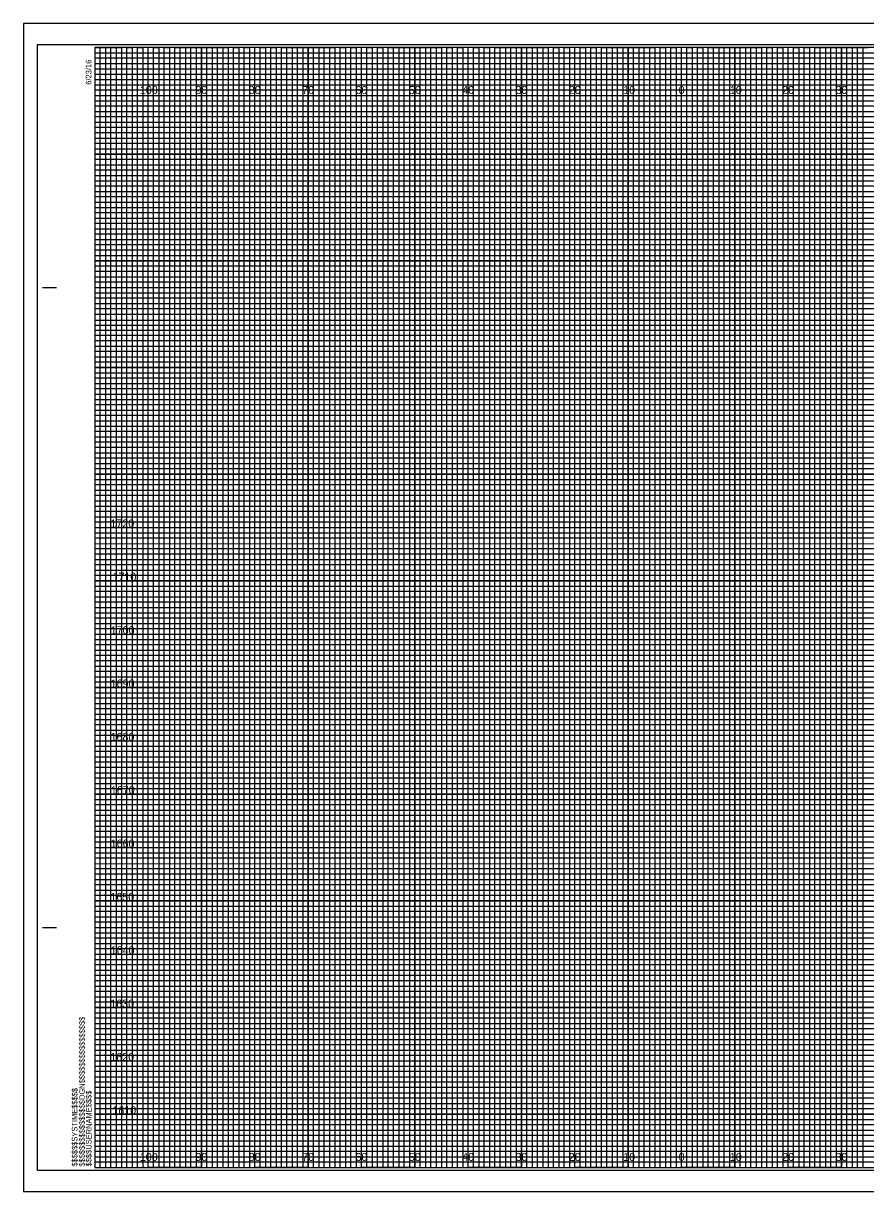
# Model space of a CAD drawing. Extents: x -13 to 323, y -5 to 6154.
# Drawn here: x -13.4 to 144.5, y 3515.5 to 3734.5 of the extents above; entities that cross this region are included whole.
import ezdxf

# ---------------------------------------------------------------- set-up
doc = ezdxf.new("R2010")
doc.units = 0
for name, color, linetype in [('Prop Retaining Wall', 7, 'Continuous'), ('Prop XS Alignment Label', 7, 'Continuous'), ('Prop XS DDE', 7, 'Continuous'), ('Prop XS DDE Elevations', 7, 'Continuous'), ('Prop XS DDE Slope Text', 7, 'Continuous'), ('Prop XS Earthwork Shape', 7, 'Continuous'), ('Prop XS Elevation Labels', 7, 'Continuous'), ('Prop XS Station Labels', 7, 'Continuous'), ('Raster_Level_0', 7, 'Continuous'), ('Scratch_Level_3', 7, 'Continuous'), ('Sheet Cutting Line CELL', 7, 'Continuous')]:
    doc.layers.add(name, color=color, linetype=linetype)

msp = doc.modelspace()

# ---------------------------------------------------------------- linework, layer by layer
at = {"layer": 'Prop Retaining Wall'}
for p, q in [((0, 3729), (260, 3729)), ((260, 3727.98), (0, 3727.98)), ((0, 3727.98), (0, 3727)), ((0, 3727), (260, 3727)), ((260, 3725.89), (0, 3725.89)), ((0, 3725.89), (0, 3724)), ((0, 3724), (320, 3724))]:
    msp.add_line(p, q, dxfattribs=at)
for points in [[(0, 3723), (270, 3723), (320, 3723), (320, 3722), (0, 3722)], [(0, 3721), (320, 3721), (320, 3719), (0, 3719)], [(0, 3718), (320, 3718), (320, 3717), (0, 3716.98)], [(0, 3716), (320, 3716), (320, 3714), (0, 3714)], [(0, 3713), (320, 3713), (320, 3712), (0, 3712)], [(0, 3711), (320, 3711), (320, 3709), (0, 3709)], [(0, 3708), (320, 3708), (320, 3707), (0, 3707)], [(0, 3706), (320, 3706), (320, 3704), (0, 3704)], [(0, 3703), (320, 3703), (320, 3702), (0, 3702)], [(0, 3701), (320, 3701), (320, 3699), (0, 3699)], [(0, 3698), (320, 3698), (320, 3697), (0, 3697)], [(0, 3696), (320, 3696), (320, 3693.95), (320, 3693), (320, 3692), (0, 3692)], [(0, 3694), (320, 3694), (320, 3693), (0, 3693)], [(0, 3691), (320, 3691), (320, 3689), (0, 3689.03)], [(0, 3689.03), (320, 3689), (320, 3688), (0, 3688)], [(0, 3687), (320, 3687), (320, 3686), (0, 3686)], [(0, 3684), (320, 3684), (320, 3683), (0, 3683)], [(0, 3682), (320, 3682), (320, 3681), (0, 3681)], [(-0.07, 3678.89), (320, 3678.89), (320, 3677.88), (-0.07, 3677.88)], [(0, 3677), (320, 3677), (320, 3676), (0, 3676)], [(0, 3674), (320, 3674), (320, 3673), (0, 3673)], [(0, 3672), (320, 3672), (320, 3671), (0, 3671)], [(0, 3669), (320, 3669), (320, 3668), (0, 3668)], [(0, 3667), (320, 3667), (320, 3666), (0, 3666)], [(0, 3664), (320, 3664), (320, 3663), (0, 3663)], [(0, 3662), (320, 3662), (320, 3661), (0, 3661)], [(0, 3659), (320, 3659), (319.99, 3657.98), (0, 3658)], [(0, 3657), (320, 3657), (320, 3656), (0, 3656)], [(0, 3654), (320, 3654), (320, 3653), (0, 3653)], [(0, 3652), (320, 3652), (320, 3651), (0, 3651)], [(0, 3649), (320, 3649), (320, 3648), (0, 3648)], [(0, 3647), (320, 3647), (320, 3646), (0, 3646)], [(0, 3644), (320, 3644), (320, 3643), (0, 3643)], [(0, 3642), (320, 3642), (320, 3641), (0, 3641)], [(0, 3639), (320, 3639), (320, 3638), (0, 3638)], [(0, 3636.99), (320.07, 3636.91), (320, 3636), (0, 3636)], [(0, 3634), (320, 3634), (320, 3633), (0, 3633)], [(0, 3632), (320, 3632), (320, 3631), (0, 3631)], [(0, 3629), (320, 3629), (320, 3628), (0, 3628)], [(0, 3627), (320, 3627), (320, 3626), (0, 3626)], [(0, 3624), (320, 3624), (320, 3623), (0, 3623)], [(0, 3622), (320, 3622), (320, 3621), (0, 3621)], [(0, 3619), (320, 3619), (320, 3618), (0, 3618)], [(0, 3617), (320, 3617), (320, 3616), (0, 3616)], [(0, 3614), (320, 3614), (320, 3613), (0, 3613)], [(0, 3612), (320, 3612), (320, 3611), (0, 3611)], [(0, 3609), (320, 3609), (320, 3608), (0, 3608)], [(0, 3607), (320, 3607), (320, 3606), (0, 3606)], [(0, 3604), (320, 3604), (320, 3603), (0, 3603)], [(0, 3602), (320, 3602), (320, 3601), (0, 3601)], [(0, 3599), (320, 3599), (319.99, 3597.98), (0, 3598)], [(0, 3597), (320, 3597), (320, 3596), (0, 3596)], [(0, 3594), (320, 3594), (320, 3593), (0, 3593)], [(0, 3592), (320, 3592), (320, 3591), (0, 3591)], [(0, 3589), (320, 3589), (320, 3588), (0, 3588)], [(0, 3587), (320, 3587), (320, 3586), (0, 3586)], [(0, 3584), (320, 3584), (320, 3583), (0, 3583)], [(0, 3582), (320, 3582), (320, 3581), (0, 3581)], [(0, 3579), (320, 3579), (320, 3578), (0, 3578)], [(0, 3576.99), (320.07, 3576.91), (320, 3576), (0, 3576)], [(0, 3574), (320, 3574), (320, 3573), (0, 3573)], [(0, 3572), (320, 3572), (320, 3571), (0, 3571)], [(0, 3569), (320, 3569), (320, 3568), (0, 3568)], [(0, 3567), (320, 3567), (320, 3566), (0, 3566)], [(0, 3564), (320, 3564), (320, 3563), (0, 3563)], [(0, 3562), (320, 3562), (320, 3561), (0, 3561)], [(0, 3559), (320, 3559), (320, 3558), (0, 3558)], [(0, 3557), (320, 3557), (320, 3556), (0, 3556)], [(0, 3554), (320, 3554), (320, 3553), (0, 3553)], [(0, 3552), (320, 3552), (320, 3551), (0, 3551)], [(0, 3549), (320, 3549), (320, 3548), (0, 3548)], [(0, 3547), (320, 3547), (320, 3546), (0, 3546)], [(0, 3544), (320, 3544), (320, 3543), (0, 3543)], [(0, 3542), (320, 3542), (320, 3541), (0, 3541)], [(0, 3539), (320, 3539), (320, 3538), (0, 3538)], [(0, 3537), (320, 3537), (320, 3536), (0, 3536)], [(0, 3534), (320, 3534), (320, 3533), (0, 3533)], [(0, 3532), (320, 3532), (320, 3531), (0, 3531)], [(0, 3529), (320, 3529), (320, 3528), (0, 3528)], [(0, 3527), (320, 3527), (320, 3526), (0, 3526)], [(0, 3524), (320, 3524), (320, 3523), (0, 3523)], [(0, 3522), (320, 3522), (320, 3521), (0, 3521)]]:
    msp.add_lwpolyline(points, dxfattribs=at)
at = {"layer": 'Prop XS Alignment Label'}
for p, q in [((-9.8, 3685), (-7.3, 3685)), ((-9.7, 3685), (-7.2, 3685)), ((-9.8, 3565), (-7.3, 3565)), ((-9.7, 3565), (-7.2, 3565)), ((0, 3520), (0, 3520)), ((0, 3520), (0, 3520)), ((0, 3520), (0, 3520)), ((0, 3520), (0, 3520)), ((0, 3520), (0, 3520)), ((0, 3520), (0, 3520)), ((0, 3520), (0, 3520))]:
    msp.add_line(p, q, dxfattribs=at)
msp.add_lwpolyline([(320, 3730), (0, 3730), (0, 3520), (320, 3520)], close=True, dxfattribs=at)
at = {"layer": 'Prop XS DDE'}
msp.add_lwpolyline([(-13.4, 3515.5), (323.3, 3515.5), (323.3, 3734.5), (-13.4, 3734.5)], close=True, dxfattribs=at)
at = {"layer": 'Prop XS DDE Elevations'}
for p, q in [((10, 3520), (10, 3730)), ((20, 3520), (20, 3730)), ((30, 3520), (30, 3730)), ((40, 3520), (40, 3730)), ((50, 3520), (50, 3730)), ((60, 3520), (60, 3730)), ((70, 3520), (70, 3730)), ((80, 3520), (80, 3730)), ((90, 3520), (90, 3730)), ((100, 3520), (100, 3730)), ((110, 3520), (110, 3730)), ((120, 3520), (120, 3730)), ((130, 3520), (130, 3730)), ((140, 3520), (140, 3730)), ((0, 3720), (320, 3720)), ((0, 3710), (320, 3710)), ((0, 3700), (320, 3700)), ((0, 3690), (320, 3690)), ((0, 3680), (320, 3680)), ((0, 3670), (320, 3670)), ((0, 3660), (320, 3660)), ((0, 3650), (320, 3650)), ((0, 3640), (320, 3640)), ((0, 3630), (320, 3630)), ((0, 3620), (320, 3620)), ((0, 3610), (320, 3610)), ((0, 3600), (320, 3600)), ((0, 3590), (320, 3590)), ((0, 3580), (320, 3580)), ((0, 3570), (320, 3570)), ((0, 3560), (320, 3560)), ((0, 3550), (320, 3550)), ((0, 3540), (320, 3540)), ((0, 3530), (320, 3530))]:
    msp.add_line(p, q, dxfattribs=at)
at = {"layer": 'Prop XS DDE Slope Text'}
msp.add_lwpolyline([(-10.8, 3519.5), (322.4, 3519.5), (322.4, 3730.5), (-10.8, 3730.5)], close=True, dxfattribs=at)
at = {"layer": 'Prop XS Earthwork Shape'}
for p, q in [((10, 3730), (0, 3730)), ((10, 3520), (10, 3730)), ((30, 3730), (20, 3730)), ((20, 3730), (20, 3520)), ((30, 3520), (30, 3730)), ((50, 3730), (40, 3730)), ((40, 3730), (40, 3520)), ((50, 3520), (50, 3730)), ((70, 3730), (60, 3730)), ((60, 3730), (60, 3520)), ((70, 3520), (70, 3730)), ((90, 3730), (80, 3730)), ((80, 3730), (80, 3520)), ((90, 3520), (90, 3730)), ((110, 3730), (100, 3730)), ((100, 3730), (100, 3520)), ((110, 3520), (110, 3730)), ((130, 3730), (120, 3730)), ((120, 3730), (120, 3520)), ((130, 3520), (130, 3730)), ((150, 3730), (140, 3730)), ((140, 3730), (140, 3520)), ((20, 3520), (10, 3520)), ((40, 3520), (30, 3520)), ((60, 3520), (50, 3520)), ((80, 3520), (70, 3520)), ((100, 3520), (90, 3520)), ((120, 3520), (110, 3520)), ((140, 3520), (130, 3520))]:
    msp.add_line(p, q, dxfattribs=at)
for points in [[(0, 3720), (320, 3720), (320, 3710), (0, 3710)], [(0, 3700), (320, 3700), (320, 3690), (0, 3690)], [(0, 3680), (320, 3680), (320, 3670), (0, 3670)], [(0, 3660), (320, 3660), (320, 3650), (0, 3650)], [(0, 3640), (320, 3640), (320, 3630), (0, 3630)], [(0, 3620), (320, 3620), (320, 3610), (0, 3610)], [(0, 3600), (320, 3600), (320, 3590), (0, 3590)], [(0, 3580), (320, 3580), (320, 3570), (0, 3570)], [(0, 3560), (320, 3560), (320, 3550), (0, 3550)], [(0, 3540), (320, 3540), (320, 3530), (0, 3530)]]:
    msp.add_lwpolyline(points, dxfattribs=at)
at = {"layer": 'Prop XS Elevation Labels'}
for points in [[(0, 3520), (1, 3520), (1, 3730), (2, 3730), (2, 3520)], [(2, 3520), (3, 3520), (3, 3730), (4, 3730), (4, 3520)], [(5, 3520), (6, 3520), (6, 3730), (7, 3730), (7, 3520)], [(7, 3520), (8, 3520), (8, 3730), (9, 3730), (9, 3520)], [(10, 3520), (11, 3520), (11, 3730), (12, 3730), (12, 3520)], [(12, 3520), (13, 3520), (13, 3730), (14, 3730), (14, 3520)], [(15, 3520), (16, 3520), (16, 3730), (17, 3730), (17, 3520)], [(17, 3520), (18, 3520), (18, 3730), (19, 3730), (19, 3520)], [(20, 3520), (21, 3520), (21, 3730), (22, 3730), (22, 3520)], [(22, 3520), (23, 3520), (23, 3730), (24, 3730), (24, 3520)], [(25, 3520), (26, 3520), (26, 3730), (27, 3730), (27, 3520)], [(27, 3520), (28, 3520), (28, 3730), (29, 3730), (29, 3520)], [(30, 3520), (31, 3520), (31, 3730), (32, 3730), (32, 3520)], [(32, 3520), (33, 3520), (33, 3730), (34, 3730), (34, 3520)], [(35, 3520), (36, 3520), (36, 3730), (37, 3730), (37, 3520)], [(37, 3520), (38, 3520), (38, 3730), (39, 3730), (39, 3520)], [(40, 3520), (41, 3520), (41, 3730), (42, 3730), (42, 3520)], [(42, 3520), (43, 3520), (43, 3730), (44, 3730), (44, 3520)], [(45, 3520), (46, 3520), (46, 3730), (47, 3730), (47, 3520)], [(47, 3520), (48, 3520), (48, 3730), (49, 3730), (49, 3520)], [(50, 3520), (51, 3520), (51, 3730), (52, 3730), (52, 3520)], [(52, 3520), (53, 3520), (53, 3730), (54, 3730), (54, 3520)], [(55, 3520), (56, 3520), (56, 3730), (57, 3730), (57, 3520)], [(57, 3520), (58, 3520), (58, 3730), (59, 3730), (59, 3520)], [(60, 3520), (61, 3520), (61, 3730), (62, 3730), (62, 3520)], [(62, 3520), (63, 3520), (63, 3730), (64, 3730), (64, 3520)], [(65, 3520), (66, 3520), (66, 3730), (67, 3730), (67, 3520)], [(67, 3520), (68, 3520), (68, 3730), (69, 3730), (69, 3520)], [(70, 3520), (71, 3520), (71, 3730), (72, 3730), (72, 3520)], [(72, 3520), (73, 3520), (73, 3730), (74, 3730), (74, 3520)], [(75, 3520), (76, 3520), (76, 3730), (77, 3730), (77, 3520)], [(77, 3520), (78, 3520), (78, 3730), (79, 3730), (79, 3520)], [(80, 3520), (81, 3520), (81, 3730), (82, 3730), (82, 3520)], [(82, 3520), (83, 3520), (83, 3730), (84, 3730), (84, 3520)], [(85, 3520), (86, 3520), (86, 3730), (87, 3730), (87, 3520)], [(87, 3520), (88, 3520), (88, 3730), (89, 3730), (89, 3520)], [(90, 3520), (91, 3520), (91, 3730), (92, 3730), (92, 3520)], [(92, 3520), (93, 3520), (93, 3730), (94, 3730), (94, 3520)], [(95, 3520), (96, 3520), (96, 3730), (97, 3730), (97, 3520)], [(97, 3520), (98, 3520), (98, 3730), (99, 3730), (99, 3520)], [(100, 3520), (101, 3520), (101, 3730), (102, 3730), (102, 3520)], [(102, 3520), (103, 3520), (103, 3730), (104, 3730), (104, 3520)], [(105, 3520), (106, 3520), (106, 3730), (107, 3730), (107, 3520)], [(107, 3520), (108, 3520), (108, 3730), (109, 3730), (109, 3520)], [(110, 3520), (111, 3520), (111, 3730), (112, 3730), (112, 3520)], [(112, 3520), (113, 3520), (113, 3730), (114, 3730), (114, 3520)], [(115, 3520), (116, 3520), (116, 3730), (117, 3730), (117, 3520)], [(117, 3520), (118, 3520), (118, 3730), (119, 3730), (119, 3520)], [(120, 3520), (121, 3520), (121, 3730), (122, 3730), (122, 3520)], [(122, 3520), (123, 3520), (123, 3730), (124, 3730), (124, 3520)], [(125, 3520), (126, 3520), (126, 3730), (127, 3730), (127, 3520)], [(127, 3520), (128, 3520), (128, 3730), (129, 3730), (129, 3520)], [(130, 3520), (131, 3520), (131, 3730), (132, 3730), (132, 3520)], [(132, 3520), (133, 3520), (133, 3730), (134, 3730), (134, 3520)], [(135, 3520), (136, 3520), (136, 3730), (137, 3730), (137, 3520)], [(137, 3520), (138, 3520), (138, 3730), (139, 3730), (139, 3520)], [(140, 3520), (141, 3520), (141, 3730), (142, 3730), (142, 3520)], [(142, 3520), (143, 3520), (143, 3730), (144, 3730), (144, 3520)]]:
    msp.add_lwpolyline(points, dxfattribs=at)
at = {"layer": 'Prop XS Station Labels'}
for points in [[(0, 3730), (5, 3730), (5, 3520), (15, 3520), (15, 3730), (25, 3730), (25, 3520), (35, 3520), (35, 3730), (45, 3730), (45, 3520), (55, 3520), (55, 3730), (65, 3730), (65, 3520), (75, 3520), (75, 3730), (85, 3730), (85, 3520), (95, 3520), (95, 3730), (105, 3730), (105, 3520), (115, 3520), (115, 3730), (125, 3730), (125, 3520), (135, 3520), (135, 3730), (145, 3730)], [(0, 3725), (275, 3725)], [(0, 3705), (320, 3705), (320, 3715), (0, 3715)], [(0, 3685), (320, 3685), (320, 3695), (0, 3695)], [(0, 3665), (320, 3665), (320, 3675), (0, 3675)], [(0, 3645), (320, 3645), (320, 3655), (0, 3655)], [(0, 3625), (320, 3625), (320, 3635), (0, 3635)], [(0, 3605), (320, 3605), (320, 3615), (0, 3615)], [(0, 3585), (320, 3585), (320, 3595), (0, 3595)], [(0, 3565), (320, 3565), (320, 3575), (0, 3575)], [(0, 3545), (320, 3545), (320, 3555), (0, 3555)], [(0, 3525), (320, 3525), (320, 3535), (0, 3535)]]:
    msp.add_lwpolyline(points, dxfattribs=at)
at = {"layer": 'Sheet Cutting Line CELL'}
for p, q in [((323.3, 3734.5), (-13.4, 3734.5)), ((-13.4, 3734.5), (-13.4, 3515.5)), ((-13.4, 3515.5), (323.3, 3515.5))]:
    msp.add_line(p, q, dxfattribs=at)

# ---------------------------------------------------------------- texts
at = {"layer": 'Prop XS Alignment Label'}
for s, p in [('6/23/16', (-0.65, 3723)), ('$$$$$$$$$$$$$$$$DGN$$$$$$$$$$$$$$$$', (-1.88, 3520.18)), ('$$$$$$SYSTIME$$$$$', (-3.26, 3520.18)), ('$$$$USERNAME$$$$', (-0.62, 3520.23))]:
    msp.add_text(s, height=1.05, rotation=90, dxfattribs=at).set_placement(p)
at = {"layer": 'Raster_Level_0'}
for s, p in [('100', (8.44, 3721.25)), ('90', (18.86, 3721.25)), ('80', (28.86, 3721.25)), ('70', (38.86, 3721.25)), ('60', (48.86, 3721.25)), ('50', (58.86, 3721.25)), ('40', (68.86, 3721.25)), ('30', (78.86, 3721.25)), ('20', (88.86, 3721.25)), ('10', (99.04, 3721.25)), ('0', (109.45, 3721.25)), ('0', (109.45, 3721.25)), ('10', (119.04, 3721.25)), ('20', (128.86, 3721.25)), ('30', (138.86, 3721.25)), ('100', (8.44, 3521.25)), ('90', (18.86, 3521.25)), ('80', (28.86, 3521.25)), ('70', (38.86, 3521.25)), ('60', (48.86, 3521.25)), ('50', (58.86, 3521.25)), ('40', (68.86, 3521.25)), ('30', (78.86, 3521.25)), ('20', (88.86, 3521.25)), ('10', (99.04, 3521.25)), ('0', (109.45, 3521.25)), ('0', (109.45, 3521.25)), ('10', (119.04, 3521.25)), ('20', (128.86, 3521.25)), ('30', (138.86, 3521.25))]:
    msp.add_text(s, height=1.5, dxfattribs=at).set_placement(p)
at = {"layer": 'Scratch_Level_3'}
for s, p in [('1720', (2.93, 3640)), ('1710', (3.31, 3630)), ('1700', (2.98, 3620)), ('1690', (2.97, 3610)), ('1680', (2.95, 3600)), ('1670', (3, 3590)), ('1660', (2.97, 3580)), ('1650', (2.92, 3570)), ('1640', (2.97, 3560)), ('1630', (2.89, 3550)), ('1620', (2.9, 3540)), ('1610', (3.28, 3530))]:
    msp.add_text(s, height=1.5, dxfattribs=at).set_placement(p)

doc.saveas('drawing.dxf')
